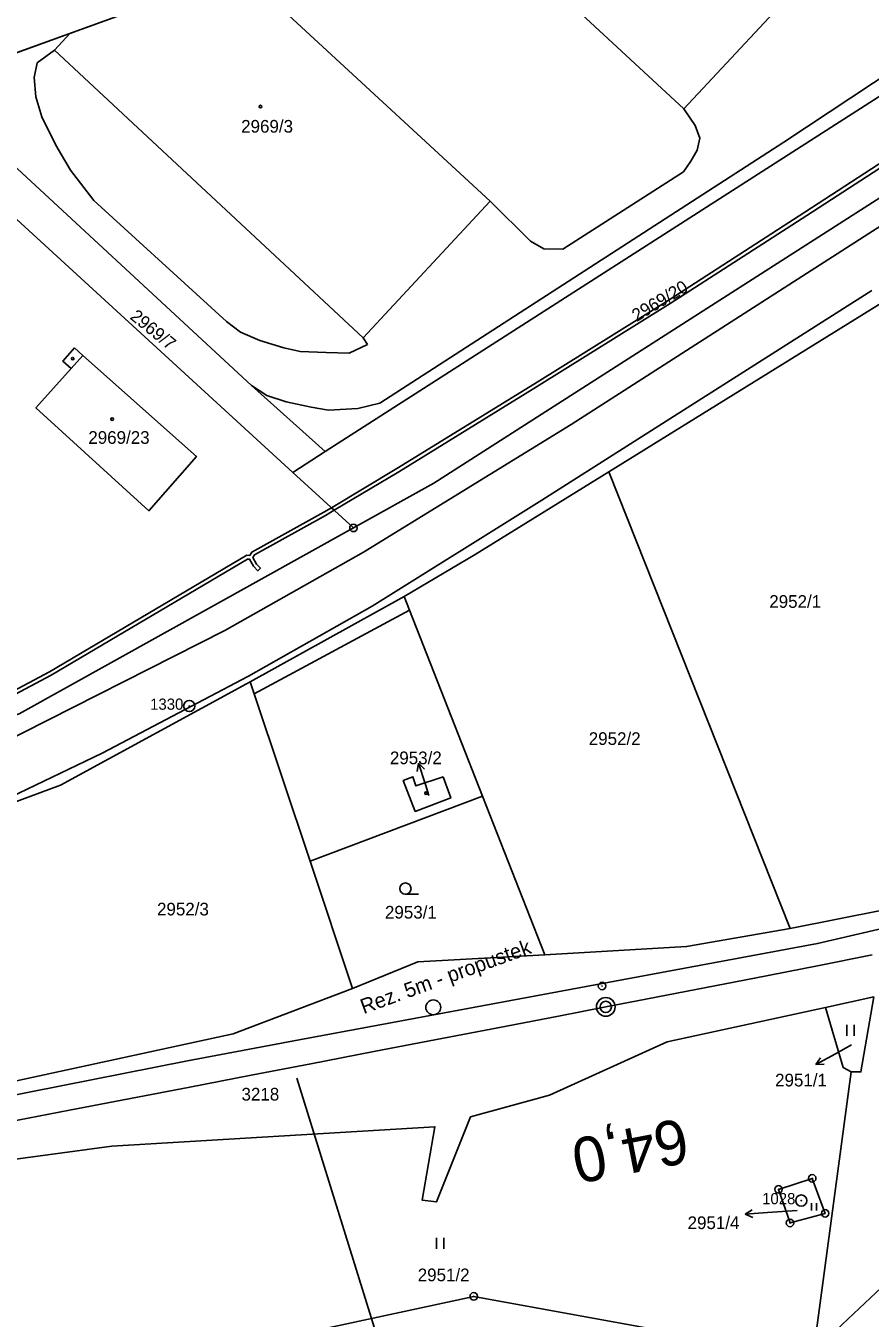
# Model space of a CAD drawing. Extents: x -620552 to -620056, y -1123312 to -1122890.
# Drawn here: x -620409.1 to -620295.9, y -1123150.9 to -1122977.7 of the extents above; entities that cross this region are included whole.
import ezdxf

# ---------------------------------------------------------------- set-up
doc = ezdxf.new("R2010")
doc.units = 0
for name, color, linetype in [('HranDP', 7, 'Continuous'), ('Hranice parcel', 7, 'Continuous'), ('Parcelní čísla', 7, 'Continuous'), ('Pop  PČ popisy', 7, 'Continuous'), ('Rámečky', 7, 'Continuous'), ('Rámečky-tisk', 7, 'Continuous'), ('Vnitřní kresba', 7, 'Continuous'), ('Vrstva 1', 7, 'Continuous'), ('Vrstva 13', 7, 'Continuous'), ('Vrstva 19', 7, 'Continuous'), ('Vrstva 3', 7, 'Continuous'), ('Vrstva 7', 7, 'Continuous'), ('Věcná břemena k části', 7, 'Continuous'), ('Značky bodu BP', 7, 'Continuous'), ('Značky budov', 7, 'Continuous'), ('Značky kultur', 7, 'Continuous')]:
    doc.layers.add(name, color=color, linetype=linetype)

msp = doc.modelspace()

# ---------------------------------------------------------------- linework, layer by layer
at = {"layer": 'HranDP'}
for p, q in [((-620306.69, -1123098.69), (-620294.3, -1123096.22)), ((-620301.93, -1123109.26), (-620295.45, -1123107.86))]:
    msp.add_line(p, q, dxfattribs=at)
for points in [[(-620339.56, -1123102.2), (-620320.55, -1123101.1), (-620306.69, -1123098.69)], [(-620339.56, -1123102.2), (-620356.6, -1123103.13), (-620365.33, -1123106.73)], [(-620420.55, -1123121.3), (-620381.33, -1123112.8), (-620365.33, -1123106.73)], [(-620301.93, -1123109.26), (-620323.18, -1123113.87), (-620338.92, -1123121.01), (-620349.51, -1123123.93), (-620354.07, -1123135.32), (-620356.01, -1123135.09), (-620354.3, -1123125.25), (-620397.61, -1123127.84), (-620420.8, -1123130.97)]]:
    msp.add_lwpolyline(points, dxfattribs=at)
at = {"layer": 'Hranice parcel'}
for p, q in [((-620369, -1123034.76), (-620282.4, -1122979.23)), ((-620373.35, -1123037.54), (-620421.73, -1122993.23)), ((-620289.02, -1123011.5), (-620330.98, -1123037.45)), ((-620373.35, -1123037.54), (-620369, -1123034.76)), ((-620365.22, -1123044.99), (-620373.35, -1123037.54)), ((-620330.98, -1123037.45), (-620306.69, -1123098.69)), ((-620358.43, -1123054.16), (-620379.05, -1123065.63)), ((-620306.69, -1123098.69), (-620294.3, -1123096.22)), ((-620301.93, -1123109.26), (-620295.45, -1123107.86)), ((-620303.5, -1123155.32), (-620298.49, -1123117.9))]:
    msp.add_line(p, q, dxfattribs=at)
for points in [[(-620325.34, -1122950.49), (-620303.81, -1122970.47), (-620320.91, -1122988.8), (-620351.92, -1122960.11)], [(-620380.28, -1122970.38), (-620346.89, -1123001.2)], [(-620346.89, -1123001.2), (-620363.9, -1123019.53), (-620405.31, -1122980.94), (-620403.21, -1122978.69)], [(-620419.67, -1122988.35), (-620410.26, -1122996.87), (-620378.87, -1123025.88), (-620369, -1123034.76)], [(-620365.22, -1123044.99), (-620354.45, -1123039), (-620287.33, -1122996.04)], [(-620402.6, -1123020.87), (-620401.48, -1123021.87), (-620386.27, -1123035.43), (-620392.63, -1123042.68), (-620407.79, -1123028.9), (-620403.06, -1123023.63), (-620404.19, -1123022.62), (-620402.6, -1123020.87)], [(-620330.98, -1123037.45), (-620348.88, -1123048.53), (-620358.43, -1123054.16)], [(-620448.18, -1123082.73), (-620410.01, -1123069.89), (-620365.22, -1123044.99)], [(-620358.43, -1123054.16), (-620357.7, -1123056.02), (-620347.91, -1123080.94), (-620339.56, -1123102.2)], [(-620379.05, -1123065.63), (-620404.47, -1123079.48), (-620414.05, -1123083.02)], [(-620365.33, -1123106.73), (-620371.02, -1123089.67), (-620378.51, -1123067.23), (-620379.05, -1123065.63)], [(-620353.21, -1123078.36), (-620352.17, -1123081.18), (-620356.92, -1123082.98), (-620358.53, -1123078.86), (-620357.25, -1123078.34), (-620356.83, -1123079.58), (-620353.21, -1123078.36)], [(-620339.56, -1123102.2), (-620320.55, -1123101.1), (-620306.69, -1123098.69)], [(-620339.56, -1123102.2), (-620356.6, -1123103.13), (-620365.33, -1123106.73)], [(-620267.31, -1123105.13), (-620271.09, -1123121.69), (-620283, -1123136.04), (-620303.5, -1123155.32)], [(-620420.55, -1123121.3), (-620381.33, -1123112.8), (-620365.33, -1123106.73)], [(-620298.49, -1123117.9), (-620297.19, -1123117.91), (-620295.45, -1123107.86)], [(-620301.93, -1123109.26), (-620323.18, -1123113.87), (-620338.92, -1123121.01), (-620349.51, -1123123.93), (-620354.07, -1123135.32), (-620356.01, -1123135.09), (-620354.3, -1123125.25), (-620397.61, -1123127.84), (-620420.8, -1123130.97)], [(-620298.49, -1123117.9), (-620299.58, -1123117.29), (-620301.93, -1123109.26)], [(-620301.98, -1123136.86), (-620306.69, -1123138.15), (-620308.23, -1123133.65), (-620303.71, -1123132.17), (-620301.98, -1123136.86)], [(-620390.82, -1123156.97), (-620349.09, -1123147.99), (-620304.63, -1123156.08), (-620303.63, -1123156.28)]]:
    msp.add_lwpolyline(points, dxfattribs=at)
at = {"layer": 'Pop  PČ popisy'}
for p, q in [((-620356.5, -1123076.52), (-620356.66, -1123077.62)), ((-620355.57, -1123079.37), (-620356.5, -1123076.52)), ((-620356.5, -1123076.52), (-620355.71, -1123077.31)), ((-620355.09, -1123080.85), (-620355.57, -1123079.37)), ((-620298.45, -1123114.27), (-620300.59, -1123115.47)), ((-620300.59, -1123115.47), (-620303.21, -1123116.93)), ((-620303.21, -1123116.93), (-620302.58, -1123116)), ((-620303.21, -1123116.93), (-620302.1, -1123116.88)), ((-620312.71, -1123136.97), (-620311.75, -1123136.4)), ((-620309.72, -1123136.76), (-620312.71, -1123136.97)), ((-620312.71, -1123136.97), (-620311.68, -1123137.4)), ((-620305.74, -1123136.49), (-620309.72, -1123136.76))]:
    msp.add_line(p, q, dxfattribs=at)
at = {"layer": 'Rámečky'}
msp.add_line((-620157.19, -1122889.6), (-620552.1, -1123032.6), dxfattribs=at)
at = {"layer": 'Rámečky-tisk'}
msp.add_lwpolyline([(-620450.98, -1123311.85), (-620056.07, -1123168.86), (-620157.19, -1122889.6), (-620552.1, -1123032.6)], dxfattribs=at)
at = {"layer": 'Vnitřní kresba'}
for p, q in [((-620405.31, -1122980.94), (-620407.63, -1122982.63)), ((-620407.63, -1122982.63), (-620408.01, -1122984.62)), ((-620307.51, -1122993.27), (-620292.44, -1122983.33)), ((-620408.01, -1122984.62), (-620407.79, -1122987.2)), ((-620407.79, -1122987.2), (-620406.97, -1122989.87)), ((-620406.97, -1122989.87), (-620405.11, -1122993.68)), ((-620320.91, -1122988.8), (-620319.39, -1122991.07)), ((-620319.39, -1122991.07), (-620318.78, -1122992.75)), ((-620405.11, -1122993.68), (-620403.13, -1122997.02)), ((-620361.67, -1123028.28), (-620307.51, -1122993.27)), ((-620318.78, -1122992.75), (-620319.15, -1122994.37)), ((-620319.15, -1122994.37), (-620319.98, -1122995.84)), ((-620403.13, -1122997.02), (-620400.01, -1123001.09)), ((-620319.98, -1122995.84), (-620320.99, -1122997.25)), ((-620320.99, -1122997.25), (-620337.13, -1123007.62)), ((-620336.04, -1123031.13), (-620285.65, -1122998.79)), ((-620400.01, -1123001.09), (-620382.25, -1123017.34)), ((-620341.49, -1123006.57), (-620346.89, -1123001.2)), ((-620339.7, -1123007.56), (-620341.49, -1123006.57)), ((-620337.13, -1123007.62), (-620339.7, -1123007.56)), ((-620339.98, -1123041.29), (-620295.72, -1123013.16)), ((-620382.25, -1123017.34), (-620380.35, -1123018.75)), ((-620380.35, -1123018.75), (-620377.77, -1123019.86)), ((-620363.32, -1123020.4), (-620363.9, -1123019.53)), ((-620377.77, -1123019.86), (-620374.53, -1123020.83)), ((-620374.53, -1123020.83), (-620372.37, -1123021.35)), ((-620372.37, -1123021.35), (-620368.87, -1123021.48)), ((-620365.77, -1123021.56), (-620363.32, -1123020.4)), ((-620403.06, -1123023.63), (-620401.48, -1123021.87)), ((-620368.87, -1123021.48), (-620365.77, -1123021.56)), ((-620376.83, -1123027.23), (-620378.87, -1123025.88)), ((-620376.83, -1123027.23), (-620374.25, -1123028.1)), ((-620374.25, -1123028.1), (-620370.88, -1123028.79)), ((-620364.63, -1123029), (-620361.67, -1123028.28)), ((-620370.88, -1123028.79), (-620368.56, -1123029.21)), ((-620368.56, -1123029.21), (-620364.63, -1123029)), ((-620363.85, -1123048.22), (-620336.04, -1123031.13)), ((-620362.71, -1123055.46), (-620339.98, -1123041.29)), ((-620382.46, -1123058.76), (-620363.85, -1123048.22)), ((-620379.28, -1123064.86), (-620362.71, -1123055.46)), ((-620357.7, -1123056.02), (-620378.51, -1123067.23)), ((-620415.29, -1123075.34), (-620382.46, -1123058.76)), ((-620398.9, -1123075.2), (-620379.28, -1123064.86)), ((-620412.3, -1123081.62), (-620398.9, -1123075.2)), ((-620371.02, -1123089.67), (-620347.91, -1123080.94))]:
    msp.add_line(p, q, dxfattribs=at)
at = {"layer": 'Vrstva 1'}
for points in [[(-620490.54, -1123135.38), (-620469.22, -1123131.24), (-620467.69, -1123132.26), (-620387.47, -1123116.43), (-620372.49, -1123113.59), (-620361.88, -1123111.62), (-620302.99, -1123100.7), (-620292.4, -1123098.24)], [(-620295.67, -1123102.19), (-620303.02, -1123103.7), (-620311.43, -1123105.36), (-620319.33, -1123106.87), (-620327.2, -1123108.39), (-620331.39, -1123109.19), (-620337.74, -1123110.43), (-620345.88, -1123111.99), (-620354.1, -1123113.57), (-620362.49, -1123115.18), (-620370.92, -1123116.8), (-620378.91, -1123118.34), (-620387.17, -1123119.94), (-620395.12, -1123121.47), (-620403.3, -1123123.04), (-620411.59, -1123124.63)]]:
    msp.add_lwpolyline(points, dxfattribs=at)
at = {"layer": 'Vrstva 13'}
msp.add_circle((-620354.51, -1123109.25), 1, dxfattribs=at)
at = {"layer": 'Vrstva 19'}
msp.add_line((-620355.01, -1123176.04), (-620372.81, -1123118.74), dxfattribs=at)
at = {"layer": 'Vrstva 7'}
msp.add_line((-620331.84, -1123106.38), (-620331.94, -1123106.4), dxfattribs=at)
for centre, radius in [((-620331.89, -1123106.39), 0.5), ((-620331.39, -1123109.19), 1.25), ((-620331.39, -1123109.19), 0.752)]:
    msp.add_circle(centre, radius, dxfattribs=at)
at = {"layer": 'Věcná břemena k části'}
msp.add_lwpolyline([(-620359.12, -1123037.46), (-620340.69, -1123026.08), (-620322.75, -1123014.93), (-620304.43, -1123003.11), (-620287.42, -1122992.06), (-620285.83, -1122990.94), (-620285.6, -1122990.17), (-620287.7, -1122991.64), (-620304.71, -1123002.69), (-620323.01, -1123014.51), (-620340.95, -1123025.66), (-620359.38, -1123037.04), (-620368.18, -1123042.28), (-620367.79, -1123042.63)], close=True, dxfattribs=at)
msp.add_lwpolyline([(-620411.29, -1123067.69), (-620405.72, -1123064.74), (-620379.41, -1123049.16), (-620379.14, -1123049.19), (-620378.61, -1123050.13), (-620378.05, -1123050.72), (-620377.69, -1123050.38), (-620378.21, -1123049.83), (-620378.69, -1123048.95), (-620378.5, -1123048.59), (-620368.96, -1123043.33), (-620367.79, -1123042.63), (-620368.18, -1123042.28), (-620369.2, -1123042.89), (-620378.86, -1123048.23), (-620379.12, -1123048.68), (-620379.53, -1123048.64), (-620405.96, -1123064.3), (-620411.49, -1123067.23)], dxfattribs=at)
at = {"layer": 'Značky bodu BP'}
for centre, radius in [((-620365.22, -1123044.99), 0.5), ((-620365.22, -1123044.99), 0.0303), ((-620387.23, -1123068.86), 0.75), ((-620387.23, -1123068.86), 0.03), ((-620303.71, -1123132.17), 0.5), ((-620303.71, -1123132.17), 0.0303), ((-620308.23, -1123133.65), 0.5), ((-620308.23, -1123133.65), 0.0303), ((-620305.18, -1123135.14), 0.75), ((-620305.18, -1123135.14), 0.03), ((-620301.98, -1123136.86), 0.5), ((-620301.98, -1123136.86), 0.0303), ((-620306.69, -1123138.15), 0.5), ((-620306.69, -1123138.15), 0.0303), ((-620349.09, -1123147.99), 0.5), ((-620349.09, -1123147.99), 0.0303)]:
    msp.add_circle(centre, radius, dxfattribs=at)
at = {"layer": 'Značky budov'}
for centre in [(-620377.67, -1122988.52), (-620402.85, -1123022.3), (-620397.57, -1123030.41), (-620355.49, -1123080.54)]:
    msp.add_circle(centre, 0.175, dxfattribs=at)
at = {"layer": 'Značky kultur'}
for p, q in [((-620358.24, -1123094.08), (-620356.49, -1123094.08)), ((-620299.07, -1123113.08), (-620299.07, -1123111.58)), ((-620298.07, -1123113.08), (-620298.07, -1123111.58)), ((-620303.81, -1123136.49), (-620303.81, -1123135.49)), ((-620303.14, -1123136.49), (-620303.14, -1123135.49)), ((-620354.1, -1123141.62), (-620354.1, -1123140.12)), ((-620353.1, -1123141.62), (-620353.1, -1123140.12))]:
    msp.add_line(p, q, dxfattribs=at)
msp.add_circle((-620358.24, -1123093.33), 0.75, dxfattribs=at)

# ---------------------------------------------------------------- texts
at = {"layer": 'Parcelní čísla'}
for s, p in [('2969/3', (-620380.27, -1122992.01)), ('2969/23', (-620400.76, -1123033.72)), ('2952/1', (-620309.47, -1123055.7)), ('2952/2', (-620333.67, -1123074.08)), ('2953/2', (-620360.33, -1123076.66)), ('2952/3', (-620391.55, -1123096.93)), ('2953/1', (-620360.99, -1123097.35)), ('2951/1', (-620308.69, -1123119.85)), ('3218', (-620380.22, -1123121.74)), ('2951/4', (-620320.42, -1123138.97)), ('2951/2', (-620356.6, -1123145.96))]:
    msp.add_text(s, height=1.7, dxfattribs=at).set_placement(p)
for s, rotation, p in [('2969/20', 31, (-620327.24, -1123017.4)), ('2969/7', 321, (-620395.29, -1123016.88))]:
    msp.add_text(s, height=1.7, rotation=rotation, dxfattribs=at).set_placement(p)
at = {"layer": 'Vrstva 3'}
msp.add_text('Rez. 5m - propustek', height=2, rotation=19.9058, dxfattribs=at).set_placement((-620363.85, -1123110.16))
at = {"layer": 'Vrstva 7'}
msp.add_text('64,0', height=6, rotation=190.9919, dxfattribs=at).set_placement((-620321, -1123124.05))
at = {"layer": 'Značky bodu BP'}
for s, p in [('1330', (-620392.48, -1123069.36)), ('1028', (-620310.43, -1123135.64))]:
    msp.add_text(s, height=1.5, dxfattribs=at).set_placement(p)

doc.saveas('drawing.dxf')
